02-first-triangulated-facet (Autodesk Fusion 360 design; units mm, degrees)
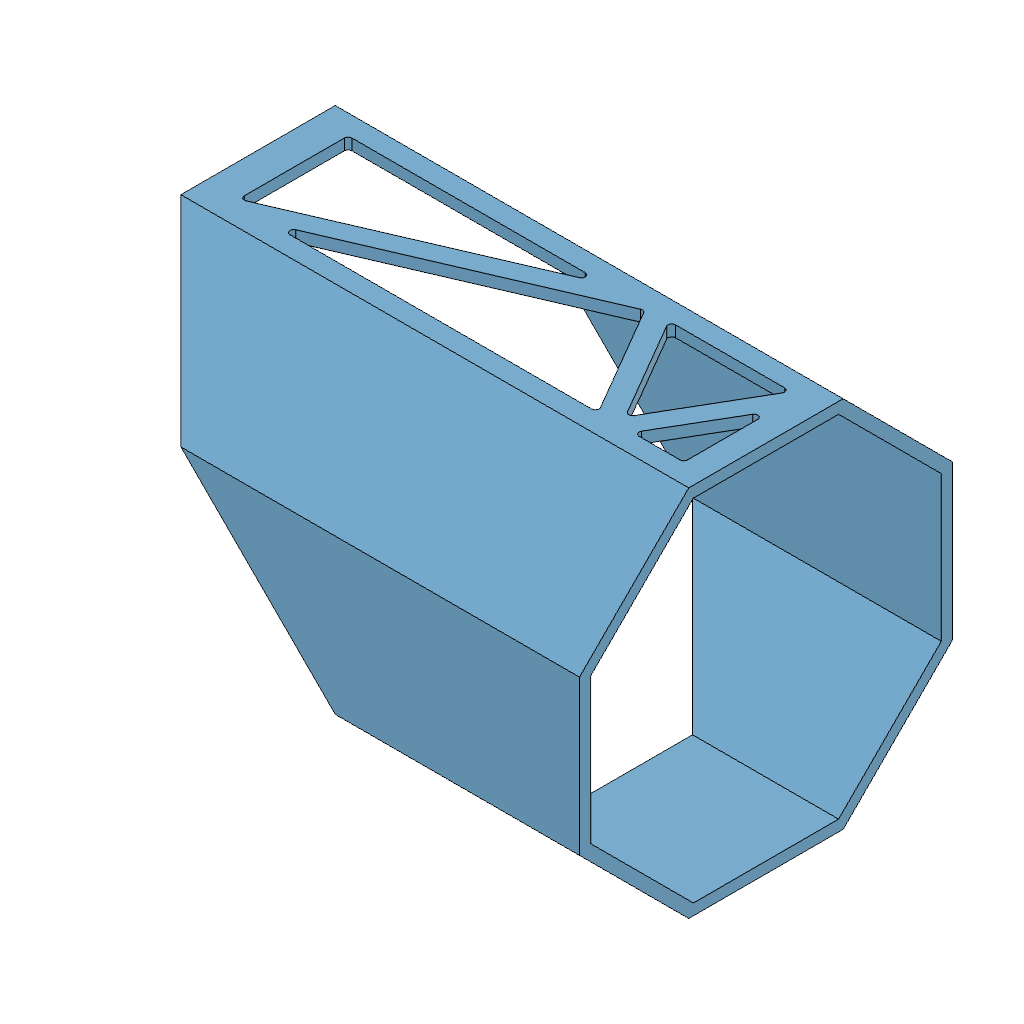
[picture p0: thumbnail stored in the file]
part number: 2026-11-02-20-17-55-344
part number: 2026-11-02-20-17-59-218
part number: 2026-11-02-20-17-59-224
parameter "bodyWidth" = 150 comment "Regular octagon across flats; corner diameter is larger."
parameter "bodyLength" = 260 comment "Overall straight length of the shared master blank."
parameter "splitAngle" = 45 comment "Keep this lesson angle at45 degrees."
parameter "faceGap" = 1 comment "Gap between the two printed joint faces."
parameter "wall" = 4.5 comment "Integrated shell and side brace radial thickness."
parameter "faceHalfWidth" = 31.066 (= "bodyWidth * ( sqrt(2) - 1 ) / 2") comment "Half-width of each outer planar facet."
parameter "memberWidth" = 8 comment "Nominal brace and corner chord width in a facet."
parameter "nodeHalfWidth" = 27.066 (= "faceHalfWidth - memberWidth / 2") comment "Chord centerlines measured from facet center."
parameter "jointNodeQ" = 7 comment "First truss skeleton row from the center joint plane."
parameter "endRim" = 10 comment "Uncut axial rim at each distant end."
parameter "endNodeX" = 124 (= "bodyLength / 2 - endRim + memberWidth / 2") comment "Last skeleton row before aperture inset."
parameter "apertureRadius" = 1.5 comment "Rounded internal corners at triangular openings."
parameter "spokeWidth" = 10 comment "Width of each deep bearing bulkhead spoke."
parameter "spokeDepth" = 18 comment "Bulkhead depth normal to the diagonal joint face."
parameter "carrierOD" = 52 comment "Outside of integrated A front bearing carrier."
parameter "rearCarrierClearance" = 46 comment "Internal carrier relief above front bearing shoulder."
parameter "tubeCornerChamfer" = 0.5 comment "Exposed outside octagon corner bevel."
parameter "tubeRimChamfer" = 0.3 comment "End rim and print-contact edge relief."
parameter "cordStation" = 125 (= "bodyLength / 2 - endRim / 2") comment "Load-test cord port center measured along body X."
parameter "bearingOD" = 22 comment "608 measured outside diameter."
parameter "bearingID" = 8 comment "608 bore."
parameter "bearingWidth" = 7 comment "608 width."
parameter "seatAllowance" = 0.2 comment "Trial DIAMETRAL clearance; choose with printed coupon."
parameter "seatDiameter" = 22.2 (= "bearingOD + seatAllowance") comment "Measured fit controls this."
parameter "coreOD" = 44 comment "Bearing holder outer diameter."
parameter "raceRelief" = 19.5 comment "Outer-ring shoulder opening; verify seals."
parameter "frontSeatDepth" = 7.1 comment "0.1 mm outer-ring axial allowance."
parameter "rearSeatDepth" = 7.2 comment "0.2 mm outer-ring axial float."
parameter "shoulder" = 3 comment "Backing behind each bearing seat."
parameter "supportSpacer" = 12 comment "Purchased metal M3 spacer length."
parameter "supportCircle" = 34 comment "Three M3 support bolts."
parameter "supportSpacerOD" = 6 comment "Purchased spacer outside diameter."
parameter "capThickness" = 3 comment "Both printed outer-ring retaining caps."
parameter "m3Clearance" = 3.3 comment "M3 through holes."
parameter "m4Clearance" = 4.3 comment "M4 through holes."
parameter "qFront" = 0.5 (= "faceGap / 2") comment "Front bearing starts at A mating face."
parameter "qFrontBack" = 10.6 (= "qFront + frontSeatDepth + shoulder") comment "End of integrated A holder."
parameter "qRearBase" = 22.6 (= "qFrontBack + supportSpacer") comment "Start of removable rear holder."
parameter "qRearBearing" = 25.6 (= "qRearBase + shoulder") comment "Rear bearing inner end."
parameter "qRearEnd" = 32.8 (= "qRearBearing + rearSeatDepth") comment "Rear holder outer end."
parameter "bearingSpacing" = 25.1 (= "qRearBearing - qFront") comment "Derived support-center spacing, not a bearing rating."
parameter "mountOD" = 76 comment "B mount and F flange outside diameter."
parameter "mountCircle" = 64 comment "Four M4 attachment holes."
parameter "mountOpening" = 50.3 comment "B through opening."
parameter "hubFace" = -23 comment "Metal hub flat mounting face."
parameter "adapterThickness" = 6 comment "F flange and metal compression sleeve length."
parameter "pilotDiameter" = 50 comment "F shallow centering pilot."
parameter "pilotInside" = 34 comment "Clearance around metal hub."
parameter "pilotHeight" = 2 comment "Short pilot only."
parameter "hubHoleSpacing" = 16 comment "Metal Sonic hub square hole spacing."
parameter "sleeveOD" = 8 comment "M4 metal compression sleeves."
parameter "sleeveAllowance" = 0.2 comment "Trial DIAMETRAL sleeve clearance."
parameter "shaftClearance" = 8.5 comment "F clearance hole; not a bearing."
parameter "nutAF" = 7.2 comment "M4 nominal 7 AF nut trial pocket."
parameter "nutDepth" = 4 comment "Open front M4 nut pocket."
parameter "rootRadius" = 1 comment "Hub-to-wall blend."
parameter "entryChamfer" = 0.4 comment "Assembly lead-in."
parameter "bedRelief" = 0.3 comment "Bed-contact edge allowance."
sketch "01 Master Octagon" plane through (0, 0, 0) normal (1, 0, 0) x axis (0, 0, -1)
  line L1 (31.066, 75) -> (75, 31.066)
  line L2 (-31.066, 75) -> (31.066, 75)
  line L3 (-75, 31.066) -> (-31.066, 75)
  line L4 (-75, -31.066) -> (-75, 31.066)
  line L5 (-31.066, -75) -> (-75, -31.066)
  line L6 (31.066, -75) -> (-31.066, -75)
  line L7 (75, -31.066) -> (31.066, -75)
  line L8 (75, 31.066) -> (75, -31.066)
  point P1 (0, 0)
  point P10 (0, 0)
  point P3 (31.066, 75)
  point P8 (31.066, -75)
  coincident P1 P10
  horizontal L2
  dimension "d59" distance P3 P8 = 150 (= "bodyWidth")
extrude "Extrude1" new body sketch "01 Master Octagon" distance 260 (= "bodyLength")
work_plane "WorkPlane1" RotateAngle 45 (= "splitAngle") ExtraOffset 0
split "Split1"
offset_faces "OffsetFaces1" distance -0.5 (= "-faceGap / 2")
offset_faces "OffsetFaces2" distance -0.5 (= "-faceGap / 2")
component_from_bodies "Body->Comp1"
component_from_bodies "Body->Comp2"
shell "Shell1" innerThickness 4.5 (= "wall")
shell "Shell1" innerThickness 4.5 (= "wall")
work_plane "WorkPlane1" RotateAngle -90 ExtraOffset 0
work_plane "WorkPlane2" AlongDistance 75 (= "bodyWidth / 2") ExtraOffset 0
sketch "A Facet 0 Triangle 1" plane through (0, 75, 0) normal (0, 1, 0) x axis (1, 0, 0)
  line L1 (-65.1005, -27.066) -> (-65.1005, 27.066)
  line L2 (60.9665, 27.066) -> (-65.1005, -27.066)
  line L3 (-65.1005, 27.066) -> (60.9665, 27.066)
  line L4 (-61.1005, -20.9953) -> (-61.1005, 23.066)
  line L5 (41.513, 23.066) -> (-61.1005, -20.9953)
  line L6 (-61.1005, 23.066) -> (41.513, 23.066)
  point P1 (0, 0)
  point P2 (-65.1005, 27.066)
  point P3 (-65.1005, -27.066)
  point P4 (60.9665, 27.066)
  dimension "d72" distance P1 P2 = 65.1005 (= "Linear Dimension-2")
  dimension "d73" distance P1 P2 = 27.066 (= "Linear Dimension-3")
  dimension "d74" distance P1 P3 = 65.1005 (= "Linear Dimension-4")
  dimension "d75" distance P1 P3 = 27.066 (= "Linear Dimension-5")
  dimension "d76" distance P1 P4 = 60.9665 (= "Linear Dimension-6")
  dimension "d77" distance P1 P4 = 27.066 (= "Linear Dimension-7")
  dimension "d78" = -4 (= "-memberWidth / 2")
extrude "Extrude1" cut sketch "A Facet 0 Triangle 1" profile of L5 L6 L4 against normal blind 4.7 (magnitude of "-( wall + 0.2 mm )")
sketch "A Facet 0 Triangle 2" plane through (0, 75, 0) normal (0, 1, 0) x axis (1, 0, 0)
  line L1 (60.9665, 27.066) -> (-65.1005, -27.066)
  line L2 (92.4832, -27.066) -> (60.9665, 27.066)
  line L3 (-65.1005, -27.066) -> (92.4832, -27.066)
  line L4 (59.2912, 21.9935) -> (-45.647, -23.066)
  line L5 (85.5258, -23.066) -> (59.2912, 21.9935)
  line L6 (-45.647, -23.066) -> (85.5258, -23.066)
  point P1 (0, 0)
  point P2 (-65.1005, -27.066)
  point P3 (60.9665, 27.066)
  point P4 (92.4832, -27.066)
  dimension "d81" distance P1 P2 = 65.1005 (= "Linear Dimension-2")
  dimension "d82" distance P1 P2 = 27.066 (= "Linear Dimension-3")
  dimension "d83" distance P1 P3 = 60.9665 (= "Linear Dimension-4")
  dimension "d84" distance P1 P3 = 27.066 (= "Linear Dimension-5")
  dimension "d85" distance P1 P4 = 92.4832 (= "Linear Dimension-6")
  dimension "d86" distance P1 P4 = 27.066 (= "Linear Dimension-7")
  dimension "d87" = 4 (= "memberWidth / 2")
extrude "Extrude2" cut sketch "A Facet 0 Triangle 2" profile of L5 L6 L4 against normal blind 4.7 (magnitude of "-( wall + 0.2 mm )")
sketch "A Facet 0 Triangle 3" plane through (0, 75, 0) normal (0, 1, 0) x axis (1, 0, 0)
  line L1 (92.4832, -27.066) -> (60.9665, 27.066)
  line L2 (124, 27.066) -> (92.4832, -27.066)
  line L3 (60.9665, 27.066) -> (124, 27.066)
  line L4 (92.4832, -19.1161) -> (67.924, 23.066)
  line L5 (117.0425, 23.066) -> (92.4832, -19.1161)
  line L6 (67.924, 23.066) -> (117.0425, 23.066)
  point P1 (0, 0)
  point P2 (60.9665, 27.066)
  point P3 (92.4832, -27.066)
  point P4 (124, 27.066)
  dimension "d90" distance P1 P2 = 60.9665 (= "Linear Dimension-2")
  dimension "d91" distance P1 P2 = 27.066 (= "Linear Dimension-3")
  dimension "d92" distance P1 P3 = 92.4832 (= "Linear Dimension-4")
  dimension "d93" distance P1 P3 = 27.066 (= "Linear Dimension-5")
  dimension "d94" distance P1 P4 = 124 (= "Linear Dimension-6")
  dimension "d95" distance P1 P4 = 27.066 (= "Linear Dimension-7")
  dimension "d96" = -4 (= "-memberWidth / 2")
extrude "Extrude3" cut sketch "A Facet 0 Triangle 3" profile of L5 L6 L4 against normal blind 4.7 (magnitude of "-( wall + 0.2 mm )")
sketch "A Facet 0 Triangle 4" plane through (0, 75, 0) normal (0, 1, 0) x axis (1, 0, 0)
  line L1 (124, 27.066) -> (92.4832, -27.066)
  line L2 (124, -27.066) -> (124, 27.066)
  line L3 (92.4832, -27.066) -> (124, -27.066)
  line L4 (120, 12.2459) -> (99.4407, -23.066)
  line L5 (120, -23.066) -> (120, 12.2459)
  line L6 (99.4407, -23.066) -> (120, -23.066)
  point P1 (0, 0)
  point P2 (92.4832, -27.066)
  point P3 (124, 27.066)
  point P4 (124, -27.066)
  dimension "d99" distance P1 P2 = 92.4832 (= "Linear Dimension-2")
  dimension "d100" distance P1 P2 = 27.066 (= "Linear Dimension-3")
  dimension "d101" distance P1 P3 = 124 (= "Linear Dimension-4")
  dimension "d102" distance P1 P3 = 27.066 (= "Linear Dimension-5")
  dimension "d103" distance P1 P4 = 124 (= "Linear Dimension-6")
  dimension "d104" distance P1 P4 = 27.066 (= "Linear Dimension-7")
  dimension "d105" = 4 (= "memberWidth / 2")
extrude "Extrude4" cut sketch "A Facet 0 Triangle 4" profile of L5 L6 L4 against normal blind 4.7 (magnitude of "-( wall + 0.2 mm )")
fillet "Fillet1" radius 1.5 (= "apertureRadius")
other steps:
base_feature "Base Feature1" bodies "A Housing print"
base_feature "Base Feature1" bodies "B Moving Body print"
create_component "CreateComponent1"
reparent_decal "ReparentDecal1"
remove_body "RemoveBody1"
create_component "CreateComponent2"
reparent_decal "ReparentDecal2"
remove_body "RemoveBody2"
named bodies: "A Housing print", "B Moving Body print"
